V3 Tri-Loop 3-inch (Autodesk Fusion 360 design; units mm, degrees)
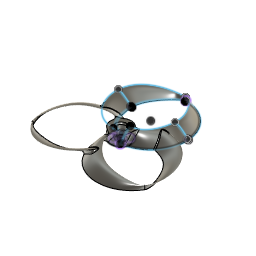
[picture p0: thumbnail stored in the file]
sketch "Hub 5mm Shaft" plane through (0, 0, 0) normal (0, 0, 1) x axis (1, 0, 0)
  circle C1 centre (0, 0) radius 2.6
  circle C2 centre (0, 0) radius 6
  point P1 (0, 0)
  point P2 (0, 0)
  coincident P1 P2
  concentric C1 C2
  dimension "d28" diameter C1 = 5.2
  dimension "d29" diameter C2 = 12
extrude "Extrude2" new body sketch "Hub 5mm Shaft" along normal blind 6 bodies "Hub 5mm Shaft"
work_plane "WorkPlane9" AlongDistance 2.5
work_plane "WorkPlane10" AlongDistance -2.5
sketch "Profile Start" plane through (2.5, 0, 0) normal (1, 0, 0) x axis (0, 1, 0)
  line L1 (-2.2, 0) -> (-3, 0)
  curve K1 (-3, 0) -> (-2.2, 0)
  curve K2 (-4, -1.5) -> (-2, 1.5)
  curve K3 (-1.2, 1.5) -> (-3.2, -1.5)
  curve K4 (2.75, 6) -> (3.25, 6)
  point P2 (-3, 0)
  point P4 (-2.2, 0)
  point P3 (3, 6)
  point P1 (0, 0)
  point P5 (-2, 1.5)
  point P8 (-1.2, 1.5)
  point P9 (3.25, 6)
  point P10 (2.75, 6)
  horizontal L1
  midpoint P2 K2
  midpoint P4 K3
  midpoint P3 K4
  dimension "d65" distance P1 P3 = 3
  dimension "d66" distance P1 P3 = 6
  dimension "d67" distance P1 P2 = 3
  dimension "d68" distance P2 P5 = 1
  dimension "d69" distance P2 P5 = 1.5
  dimension "d70" distance P4 P8 = 1.5
  dimension "d71" distance P5 P8 = 0.8
  dimension "d72" distance P9 P10 = 0.5
  dimension "d134" distance P2 P4 = 0.8
sketch "Profile End" plane through (-2.5, 0, 0) normal (1, 0, 0) x axis (0, 1, 0)
  curve K1 (3, 0) -> (2.2, 0)
  curve K2 (1.5, 1.5) -> (3.3398, -1.2565)
  curve K3 (-1.75, 5) -> (-2.25, 5)
  curve K4 (4, -1.5) -> (2, 1.5)
  line L1 (-1.75, 5) -> (-2.25, 5)
  line L2 (2.2, 0) -> (3, 0)
  point P5 (-1.75, 5)
  point P9 (-2.25, 5)
  point P4 (2.2, 0)
  point P8 (3, 0)
  point P6 (-2, 5)
  point P11 (0, 0)
  point P3 (1.5, 1.5)
  point P7 (2, 1.5)
  dimension "d84" distance P5 P9 = 0.5
  dimension "d89" distance P4 P8 = 0.8
  dimension "d101" distance P6 P11 = 5
  dimension "d102" distance P6 P11 = 2
  dimension "d103" distance P8 P11 = 3
  dimension "d104" distance P3 P11 = 1.5
  dimension "d105" distance P3 P11 = 1.5
  dimension "d106" distance P7 P11 = 2
  dimension "d107" distance P7 P11 = 1.5
sketch "Target Shape" plane through (0, 0, 0) normal (0, 0, 1) x axis (1, 0, 0)
  line L1 (7.9957, 37.405) -> (0, 0)
  line L2 (24.1826, 14.3878) -> (3.9979, 18.7025)
  line L3 (-15.6878, 22.9105) -> (3.9979, 18.7025)
  circle C1 centre (0, 0) radius 38.25
  circle C2 centre (3.9748, 17.3739) radius 20.4272
  circle C3 centre (0, 21.0408) radius 18.2132
  point P1 (0, 0)
  point P2 (0, 0)
  point P4 (2.5, -3)
  point P5 (-2.5, -2)
  point P7 (2.5, 3)
  point P8 (-2.5, 3)
  point P9 (0, 0)
  point P10 (7.9957, 37.405)
  point P11 (3.9979, 18.7025)
  point P12 (24.1826, 14.3878)
  point P13 (-15.6878, 22.9105)
  coincident P1 P2
  coincident C2 P4
  coincident C2 P5
  tangent C1 C2
  coincident C3 P7
  coincident C3 P8
  coincident P2 P9
  coincident C1 P10
  coincident C3 P10
  midpoint L1 P11
  coincident C2 P12
  perpendicular L1 L2
  coincident C2 P13
  perpendicular L1 L3
  dimension "d95" diameter C1 = 76.5
  dimension "d119" distance P11 P12 = 20.6407
sketch "Profile Edge" plane through (0, 0, 0) normal (1, 0, 0) x axis (0, 1, 0)
  line L1 (38.25, 0) -> (37.75, 0)
  curve K1 (37.75, 0) -> (38.25, 0)
  curve K2 (37.9, 2) -> (38.1, 2)
  curve K3 (38.25, 0.8) -> (38.25, -0.8)
  curve K4 (37.75, -0.8) -> (37.75, 0.8)
  point P4 (38, 2)
  point P3 (38.25, 0)
  point P2 (37.75, 0)
  point P1 (0, 0)
  point P5 (38.1, 2)
  point P6 (37.9, 2)
  horizontal L1
  midpoint P4 K2
  midpoint P3 K3
  midpoint P2 K4
  dimension "d96" distance P2 P3 = 0.5
  dimension "d98" distance P3 P4 = 2
  dimension "d121" distance P1 P4 = 2
  dimension "d138" distance P5 P6 = 0.2
work_plane "WorkPlane11" AlongDistance 19.125 (= "( 76.5 / 4 ) * 1 mm")
sketch "Profile Mid" plane through (0, 19.125, 0) normal (0, 1, 0) x axis (1, 0, 0)
  line L1 (19.8407, 0) -> (20.6407, 0)
  curve K1 (19.8407, 0) -> (20.6407, 0)
  curve K2 (12.3907, -5) -> (12.8907, -5)
  curve K3 (21.8407, 1.5) -> (17.8407, -1.5)
  curve K4 (19, -1.5) -> (22.2814, 1.5)
  line L2 (-13.4407, 0) -> (-12.6407, 0)
  curve K5 (-13.4407, 0) -> (-12.6407, 0)
  curve K6 (-14.5, -1.5) -> (-10.7814, 1.5)
  curve K7 (-20.8407, -5) -> (-20.4407, -5)
  curve K8 (-11.4407, 1.5) -> (-15.4407, -1.5)
  point P3 (12.6407, -5)
  point P4 (19.8407, 0)
  point P2 (20.6407, 0)
  point P15 (-20.6407, -5)
  point P14 (-13.4407, 0)
  point P11 (-12.6407, 0)
  point P5 (12.8907, -5)
  point P6 (12.3907, -5)
  point P1 (0, 0)
  point P18 (-20.8407, -5)
  point P19 (-20.4407, -5)
  midpoint P3 K2
  midpoint P4 K3
  midpoint P2 K4
  midpoint P15 K7
  midpoint P14 K8
  midpoint P11 K6
  dimension "d109" distance P2 P4 = 0.8
  dimension "d110" distance P2 P3 = 5
  dimension "d111" distance P2 P3 = 8
  dimension "d112" distance P5 P6 = 0.5
  dimension "d113" distance P1 P2 = 20.6407
  dimension "d114" distance P11 P14 = 0.8
  dimension "d115" distance P11 P15 = 5
  dimension "d116" distance P11 P15 = 8
  dimension "d117" distance P18 P19 = 0.4
  dimension "d118" distance P1 P15 = 20.6407
sketch "Lower Rails" plane through (0, 0, 0) normal (0, 0, 1) x axis (1, 0, 0)
  curve K1 (-2.5, 2.2) -> (0, 38.25)
  curve K2 (2, 1.7) -> (-7, 2.7)
  curve K3 (-13.45, 15) -> (-13.4314, 23.25)
  curve K4 (-1.5, 38.25) -> (1.5, 38.25)
  curve K5 (-2.5, 3) -> (0, 37.75)
  curve K6 (2, 2.5) -> (-7, 3.5)
  curve K7 (-12.6348, 15.5025) -> (-12.6466, 22.7475)
  curve K8 (-1.5, 37.75) -> (1.5, 37.75)
  arc A1 centre (-0.1724, 17.686) radius 20.0648 clockwise from (0, 37.75) to (2.5, -2.2)
  arc A2 centre (0, 17.5492) radius 20.7008 clockwise from (0, 38.25) to (2.5, -3)
  point P8 (19.8407, 19.125)
  point P9 (-13.4407, 19.125)
  point P12 (-13.4407, 19.125)
  point P10 (-2.5, 2.2)
  point P13 (-2.5, 2.2)
  point P11 (0, 38.25)
  point P5 (0, 37.75)
  point P20 (0, 37.75)
  point P21 (-12.6407, 19.125)
  point P23 (-12.6407, 19.125)
  point P4 (-2.5, 3)
  point P22 (-2.5, 3)
  point P33 (20.6407, 19.125)
  point P28 (1.5, 37.75)
  point P29 (-1.5, 37.75)
  point P18 (1.5, 38.25)
  point P19 (-1.5, 38.25)
  coincident P8 A1
  coincident P9 P12
  coincident P10 P13
  midpoint P13 K2
  midpoint P12 K3
  midpoint P11 K4
  coincident P5 P20
  coincident P21 P23
  coincident P4 P22
  midpoint P22 K6
  parallel K2 K6
  midpoint P21 K7
  midpoint P20 K8
  coincident P33 A2
  dimension "d136" distance P28 P29 = 3
  dimension "d137" distance P18 P19 = 3
work_plane "WorkPlane12" AlongDistance 6
sketch "Upper Rails" plane through (0, 0, 6) normal (0, 0, 1) x axis (1, 0, 0)
  line L1 (0, 38.25) -> (0, 37.75)
  curve K1 (2.5, 3) -> (0, 38)
  curve K2 (-1.2, 3) -> (6.2, 3)
  curve K3 (12.65, 15) -> (12.6314, 23.25)
  curve K4 (1.5, 38) -> (-1.5, 38)
  curve K5 (-2.5, -2) -> (0, 38)
  curve K6 (2, -2) -> (-7, -2)
  curve K7 (-5, 38) -> (5, 38)
  curve K8 (-20.7814, 14.25) -> (-20.5, 24)
  point P7 (2.5, 3)
  point P9 (2.5, 3)
  point P6 (12.6407, 19.125)
  point P5 (0, 38)
  point P16 (0, 38)
  point P18 (-2.5, -2)
  point P17 (-20.6407, 19.125)
  point P14 (-1.5, 38)
  point P15 (1.5, 38)
  coincident P7 P9
  midpoint P7 K2
  midpoint P6 K3
  midpoint P5 K4
  coincident P5 P16
  midpoint P18 K6
  midpoint P16 K7
  midpoint P17 K8
  dimension "d135" distance P14 P15 = 3
loft "Loft3" sketch "Profile Start" + "Profile Mid" + "Profile Edge" bodies "Blade Template 3x2.5x3"
loft "Loft4" sketch "Profile Edge" + "Profile Mid" + "Profile End"
circular_pattern "C-Pattern2" TotalAngle 360
combine "Combine2"
offset_faces "OffsetFaces5" distance -0.5
circular_pattern "C-Pattern3" TotalAngle 360
combine "Combine3"
fillet "Fillet2" radius 1
chamfer "Chamfer1" distance 0.75
copy_paste_bodies "CopyPasteBodies1"
offset_faces "OffsetFaces3" distance 2
combine "Combine4"
fillet "Fillet3" radius 2
offset_faces "OffsetFaces4" distance -2
mirror "Mirror1" mirrorStitchTolerance 0.1 bodies "3x2.5x3 CW"
copy_paste_bodies "CopyPasteBodies2"
copy_paste_bodies "CopyPasteBodies3"
scale "Scale1" ScaleX 1.1667 ScaleY 1.1667
offset_faces "OffsetFaces6" distance 2
combine "Combine5"
fillet "Fillet4" radius 1
offset_faces "OffsetFaces7" distance -2
mirror "Mirror2" mirrorStitchTolerance 0.1 bodies "3.5x2.5x3 CW"
sketch "Hub 5mm T-Mount" plane through (0, 0, 0) normal (0, 0, 1) x axis (1, 0, 0)
  circle C1 centre (0, 0) radius 6
  circle C2 centre (0, 0) radius 0.8
  circle C3 centre (2.5, 0) radius 1.05
  circle C4 centre (-2.5, 0) radius 1.05
  point P1 (0, 0)
  point P2 (0, 0)
  point P3 (0, 0)
  point P5 (-2.5, 0)
  point P4 (2.5, 0)
  coincident P1 P2
  concentric C1 C2
  dimension "d150" diameter C1 = 12
  dimension "d151" diameter C2 = 1.6
  dimension "d152" diameter C3 = 2.1
  dimension "d153" diameter C4 = 2.1
  dimension "d154" distance P3 P5 = 2.5
  dimension "d155" distance P3 P4 = 2.5
extrude "Extrude4" new body sketch "Hub 5mm T-Mount" along normal blind 6 bodies "Hub 5mm T-Mount"
chamfer "Chamfer2" distance 0.25
copy_paste_bodies "CopyPasteBodies4"
offset_faces "OffsetFaces8" distance 2
copy_paste_bodies "CopyPasteBodies5"
offset_faces "OffsetFaces10" distance -1
combine "Combine6"
combine "Combine7"
fillet "Fillet5" radius 1
offset_faces "OffsetFaces9" distance -2
chamfer "Chamfer4" distance 0.25
mirror "Mirror3" mirrorStitchTolerance 0.1 bodies "3x2.5x3T CW"
fillet "Fillet6" radius 1
offset_faces "OffsetFaces11" distance -2
chamfer "Chamfer5" distance 0.25
mirror "Mirror4" mirrorStitchTolerance 0.1 bodies "3.5x2.5x3T CW"
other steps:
base_feature "Base Feature1" bodies "Hub 5mm Shaft", "3x2.5x3 CCW"
base_feature "Base Feature2" bodies "3x2.5x3", "Blade Template 3.5x2.5x3"
base_feature "Base Feature3" bodies "Hub 5mm Shaft (1)", "3.5x2.5x3 CCW"
base_feature "Base Feature4" bodies "Hub 5mm T-Mount", "3x2.5x3T CCW"
base_feature "Base Feature5" bodies "3x2.5x3T CCW", "3.5x2.5x3T CCW"
named bodies: "Hub 5mm Shaft", "Blade Template 3x2.5x3", "3x2.5x3 CCW", "3x2.5x3 CW", "3x2.5x3", "Blade Template 3.5x2.5x3", "Hub 5mm Shaft (1)", "3.5x2.5x3 CCW", "3.5x2.5x3 CW", "Hub 5mm T-Mount", "3x2.5x3T CCW", "3.5x2.5x3T CCW", "3x2.5x3T CW", "3.5x2.5x3T CW"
